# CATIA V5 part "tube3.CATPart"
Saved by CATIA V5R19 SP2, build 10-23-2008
Part number: tube3
Bounding box of the stored display mesh (mm): x -940 to 60, y 0 to 380, z -300 to 300
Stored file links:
  M:\EU_thinkMotion\IAO_2010\iao\IAO_MMS_Groupe2\IAO_MMS_Groupe2\mayache\mayache\Pièces\tube3.CATPart
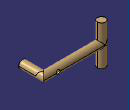
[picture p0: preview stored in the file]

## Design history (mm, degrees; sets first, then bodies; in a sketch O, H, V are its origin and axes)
Parameters
  raytube = 60 mm
  longtube1 = 320 mm
  longtube2 = 1000 mm
  longtube3 = 300 mm
Body1 (main body)
  Sketch1 on zx-plane, origin (0, 0, 0), H (-1, 0, 0), V (0, 0, 1)
    circle A1 centre (0, 0) radius 60
    point P1 (60, 0)
    radius A1 = 60 {= raytube}
    coincidence: A1 P1, P1 H
  Pad1: profile Sketch1, direction (0, 1, 0), length 380 {= raytube +longtube1}
  Plane1: type Offset, RefPlane yz-plane, Offset 60 {= raytube}
  Body2
    Sketch2 on Plane1, origin (60, 0, 0), H (0, 1, 0), V (0, 0, 1)
      circle A1 centre (320, 0) radius 60
      point P1 (320, 0)
      reference projected line E1 (0, 60) -> (0, -60) from edge [start face of Pad1 | face of Pad1 from Sketch1.A1]
      radius A1 = 60 {= raytube}
      distance P1 E1 = 320 {= longtube1}
      coincidence: P1 H
    Pad2: profile Sketch2, direction (-1, 0, 0), length 1000 {= longtube2}
  Trim1: tool Body2, faces to remove start face of Pad2; end face of Pad1
  Body3
    Sketch3 on xy-plane, origin (0, 0, 0), H (1, 0, 0), V (0, 1, 0)
      circle A1 centre (-880, 320) radius 60
      point P1 (-880, 320)
      reference intersected line E1 through (0, 0) direction (0, 1) from yz-plane
      reference projected line E2 through (0, 320) direction (1, 0) from axis of face of Pad2 from Sketch2.A1
      radius A1 = 60 {= raytube}
      distance E1 P1 = 880 {= longtube2 -2*raytube}
      distance E2 P1 = 0
    Pad3: profile Sketch3, direction (0, 0, 1), length 300 {= longtube3}, mirrored extent
  Trim2: tool Body3, faces to remove end face of Pad2
  Body4
    Plane2: type Offset, RefPlane zx-plane, Offset 365 {= longtube1 +0.75*raytube}
    Sketch4 on Plane2, origin (0, 365, 0), H (-1, 0, 0), V (0, 0, 1)
      line L1 (133.3333, 0) -> (193.3333, 0)
      point P1 (133.3333, 0)
      arc A1 centre (163.3333, 0) radius 30 from (133.3333, 0) to (193.3333, 0) cw
      distance O P1 = 133.3333 {= longtube2 /7.5}
      length L1 = 60 {= raytube}
      radius A1 = 30 {= raytube /2}
      coincidence: P1 H
      horizontal: L1 H
    Shaft1: profile Sketch4, axis Sketch4.L1, angle 360
  Remove1: tool Body4
Relations
  Plane2.Offset = longtube1 +2raytube /3 (deactivated)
